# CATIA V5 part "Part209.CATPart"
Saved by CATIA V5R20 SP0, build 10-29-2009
Part number: FA 168700-3
Revision: ANY
Definition: UNKNOWN
Nomenclature: FA 168700-3
Source: Unknown
Bounding box of the stored display mesh (mm): x -3 to 3, y 0 to 4.95, z -3.464 to 3.464
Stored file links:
  C:\Users\Utente\Desktop\IO LAVORO\3D X SITO CF\CUMSA\3D files FA\FA 200700\Part209.CATPart
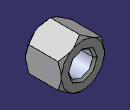
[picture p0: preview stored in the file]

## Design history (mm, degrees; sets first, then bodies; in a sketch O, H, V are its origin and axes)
Body1 "Cortar-Extruir3" (main body)
  Solid1: solid without history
